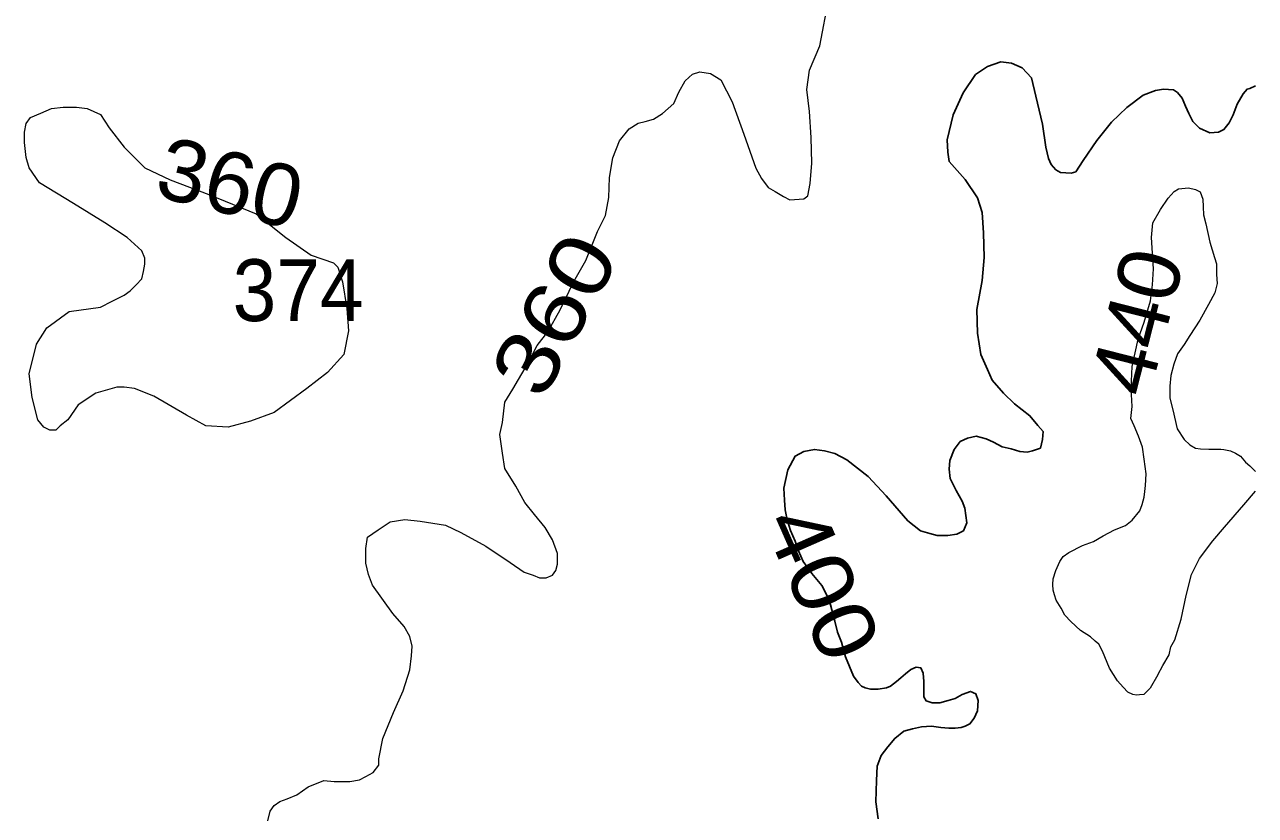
# Model space of a CAD drawing. Extents: x 445.4 to 500, y 8728.7 to 8784.
# Drawn here: x 496.816 to 500, y 8746.525 to 8748.572 of the extents above; entities that cross this region are included whole.
import ezdxf
from ezdxf.enums import TextEntityAlignment as Align

# ---------------------------------------------------------------- set-up
doc = ezdxf.new("R2010")
doc.units = 0
doc.header["$LTSCALE"] = 0.064
doc.layers.add('1', color=7, linetype='Continuous', lineweight=25)
doc.layers.add('2', color=7, linetype='Continuous', lineweight=13)
doc.layers.add('21', color=7, linetype='Continuous')
doc.layers.add('61', color=7, linetype='Continuous')

msp = doc.modelspace()

# ---------------------------------------------------------------- linework, layer by layer
at = {"layer": '1'}
for points in [[(499.1336, 8747.2619), (499.1576, 8747.255), (499.1765, 8747.2499), (499.204, 8747.2499), (499.228, 8747.2533), (499.2451, 8747.2619), (499.2537, 8747.2824), (499.2485, 8747.3201), (499.2417, 8747.3389), (499.2262, 8747.3663), (499.2108, 8747.3971), (499.2074, 8747.4211), (499.2091, 8747.4433), (499.2211, 8747.4724), (499.2365, 8747.493), (499.2554, 8747.5015), (499.2777, 8747.5067), (499.3034, 8747.4998), (499.3223, 8747.4913), (499.3446, 8747.4793), (499.3686, 8747.4742), (499.3909, 8747.4673), (499.4097, 8747.4656), (499.4235, 8747.469), (499.444, 8747.4759), (499.4492, 8747.4981), (499.4509, 8747.5187), (499.4372, 8747.5341), (499.4166, 8747.5597), (499.3772, 8747.5906), (499.348, 8747.618), (499.3192, 8747.6514), (499.3072, 8747.6788), (499.29, 8747.7182), (499.2814, 8747.7729), (499.2797, 8747.8346), (499.2934, 8747.9099), (499.2986, 8747.9692), (499.2969, 8748.0325), (499.2935, 8748.0856), (499.2815, 8748.1232), (499.2489, 8748.1712), (499.2215, 8748.202), (499.2078, 8748.2174), (499.2043, 8748.2414), (499.2026, 8748.2739), (499.218, 8748.3382), (499.2437, 8748.3947), (499.2763, 8748.4426), (499.3072, 8748.4632), (499.3415, 8748.4752), (499.3689, 8748.4717), (499.3964, 8748.4598), (499.4204, 8748.4341), (499.4324, 8748.3861), (499.4495, 8748.3143), (499.4581, 8748.2543), (499.465, 8748.2252), (499.4718, 8748.2098), (499.4838, 8748.1961), (499.4958, 8748.1893), (499.5233, 8748.1876), (499.5353, 8748.191), (499.5541, 8748.2201), (499.5902, 8748.2715), (499.6279, 8748.3194), (499.6673, 8748.357), (499.7093, 8748.3894), (499.7419, 8748.4014), (499.7625, 8748.4048), (499.7882, 8748.4031), (499.7985, 8748.3963), (499.8105, 8748.3809), (499.8191, 8748.3603), (499.8277, 8748.3415), (499.8379, 8748.321), (499.8551, 8748.3038), (499.8825, 8748.2919), (499.9048, 8748.2936), (499.9185, 8748.3004), (499.9323, 8748.3175), (499.9425, 8748.3381), (499.9528, 8748.3655), (499.9683, 8748.3929), (499.9786, 8748.4048), (499.9854, 8748.4066), (500, 8748.4131)], [(499.0243, 8746.5166), (499.0181, 8746.5609), (499.0197, 8746.6159), (499.0212, 8746.6526), (499.0319, 8746.6801), (499.0488, 8746.703), (499.0671, 8746.7244), (499.0901, 8746.7437), (499.1131, 8746.7498), (499.1361, 8746.7544), (499.1621, 8746.7559), (499.1866, 8746.7528), (499.2065, 8746.7513), (499.2233, 8746.7513), (499.2387, 8746.7528), (499.2494, 8746.7559), (499.2616, 8746.762), (499.2723, 8746.7773), (499.2815, 8746.7956), (499.2831, 8746.8231), (499.2769, 8746.84), (499.2631, 8746.8461), (499.2417, 8746.8384), (499.2233, 8746.8277), (499.205, 8746.8231), (499.1835, 8746.817), (499.1636, 8746.817), (499.1483, 8746.8216), (499.1422, 8746.8323), (499.1422, 8746.8507), (499.1422, 8746.8721), (499.1407, 8746.8935), (499.1345, 8746.9072), (499.1223, 8746.9087), (499.1085, 8746.9026), (499.0947, 8746.8919), (499.0825, 8746.8812), (499.0718, 8746.8721), (499.0564, 8746.8598), (499.0457, 8746.8552), (499.0243, 8746.8522), (499.0044, 8746.8522), (498.9906, 8746.8552), (498.9814, 8746.8598), (498.9722, 8746.869), (498.96, 8746.8858), (498.9398, 8746.9355), (498.9296, 8746.9734), (498.9193, 8746.9991), (498.9124, 8747.0282), (498.897, 8747.083), (498.8781, 8747.1206), (498.8524, 8747.1515), (498.8301, 8747.1823), (498.8181, 8747.2097), (498.8095, 8747.2353), (498.7975, 8747.2627), (498.789, 8747.2901), (498.7838, 8747.3158), (498.7821, 8747.3415), (498.7804, 8747.3723), (498.7907, 8747.4194), (498.8095, 8747.4553), (498.8318, 8747.4673), (498.8593, 8747.4724), (498.885, 8747.469), (498.9124, 8747.4622), (498.9433, 8747.4451), (498.9982, 8747.4023), (499.0445, 8747.3526), (499.1011, 8747.2876), (499.1336, 8747.2619)]]:
    msp.add_lwpolyline(points, dxfattribs=at)
at = {"layer": '2'}
for points in [[(498.7391, 8748.15), (498.758, 8748.1395), (498.779, 8748.1269), (498.7958, 8748.1186), (498.8315, 8748.1206), (498.842, 8748.129), (498.8483, 8748.1604), (498.8525, 8748.2128), (498.8504, 8748.2799), (498.8462, 8748.3469), (498.8399, 8748.4035), (498.8462, 8748.4537), (498.8735, 8748.5166), (498.8965, 8748.6402)], [(497.4449, 8746.5114), (497.4512, 8746.5365), (497.4617, 8746.5512), (497.4764, 8746.5616), (497.4953, 8746.5679), (497.5205, 8746.5784), (497.5498, 8746.5994), (497.5897, 8746.6153), (497.617, 8746.6132), (497.6569, 8746.6132), (497.6821, 8746.6174), (497.6989, 8746.6258), (497.7178, 8746.6363), (497.7325, 8746.6551), (497.7325, 8746.6719), (497.7429, 8746.7243), (497.7702, 8746.7913), (497.7954, 8746.8479), (497.8122, 8746.9023), (497.8164, 8746.938), (497.8185, 8746.9631), (497.8122, 8746.9882), (497.7975, 8747.0146), (497.7681, 8747.0481), (497.7157, 8747.1214), (497.7052, 8747.1487), (497.6989, 8747.178), (497.6989, 8747.2157), (497.7031, 8747.245), (497.7304, 8747.2639), (497.7618, 8747.2848), (497.7996, 8747.2911), (497.8395, 8747.2869), (497.9046, 8747.2765), (497.9444, 8747.2576), (498.0095, 8747.222), (498.0724, 8747.1801), (498.1081, 8747.1549), (498.1312, 8747.1466), (498.148, 8747.1403), (498.1648, 8747.1403), (498.1816, 8747.1466), (498.19, 8747.1591), (498.1942, 8747.1759), (498.1942, 8747.2031), (498.1816, 8747.2387), (498.1627, 8747.2702), (498.1354, 8747.3037), (498.1102, 8747.3351), (498.0871, 8747.377), (498.0583, 8747.4228), (498.052, 8747.4626), (498.0457, 8747.5107), (498.052, 8747.5422), (498.0583, 8747.5945), (498.0793, 8747.6281), (498.1171, 8747.693), (498.1422, 8747.7412), (498.1695, 8747.7768), (498.201, 8747.8334), (498.2367, 8747.9067), (498.2682, 8747.9612), (498.2979, 8748.0359), (498.3189, 8748.0778), (498.3273, 8748.1239), (498.3294, 8748.1762), (498.3378, 8748.2265), (498.3546, 8748.2705), (498.3797, 8748.3019), (498.4028, 8748.3166), (498.4217, 8748.3208), (498.4427, 8748.3271), (498.4658, 8748.3417), (498.4957, 8748.3678), (498.5083, 8748.3972), (498.5251, 8748.4265), (498.544, 8748.4433), (498.5628, 8748.4496), (498.5901, 8748.4454), (498.6174, 8748.4286), (498.6468, 8748.372), (498.6762, 8748.2882), (498.7077, 8748.2003), (498.7224, 8748.173), (498.7391, 8748.15)], [(499.7479, 8746.8887), (499.7275, 8746.8542), (499.7152, 8746.8413), (499.7115, 8746.8382), (499.7004, 8746.837), (499.6923, 8746.8364), (499.6831, 8746.8382), (499.6701, 8746.8444), (499.6578, 8746.8573), (499.643, 8746.8739), (499.6226, 8746.906), (499.6047, 8746.9503), (499.5947, 8746.9686), (499.5854, 8746.9766), (499.5731, 8746.9871), (499.5478, 8747.0037), (499.5225, 8747.0271), (499.507, 8747.0432), (499.4972, 8747.0616), (499.4848, 8747.082), (499.4803, 8747.0959), (499.4765, 8747.1083), (499.4759, 8747.123), (499.4772, 8747.1378), (499.484, 8747.1594), (499.4944, 8747.1822), (499.5025, 8747.1951), (499.5173, 8747.2056), (499.5526, 8747.2238), (499.581, 8747.2343), (499.6063, 8747.2485), (499.6353, 8747.2639), (499.6637, 8747.2756), (499.6816, 8747.2891), (499.7008, 8747.3131), (499.7071, 8747.3301), (499.7126, 8747.3486), (499.7139, 8747.3634), (499.7157, 8747.3794), (499.7176, 8747.4089), (499.712, 8747.4476), (499.7077, 8747.4778), (499.6978, 8747.5067), (499.6861, 8747.5338), (499.6781, 8747.5523), (499.6813, 8747.5831), (499.6787, 8747.63), (499.6813, 8747.6873), (499.697, 8747.7576), (499.7126, 8747.8018), (499.7283, 8747.8565), (499.7335, 8747.8981), (499.7361, 8747.9398), (499.7309, 8748.0205), (499.7346, 8748.0591), (499.7542, 8748.0936), (499.7747, 8748.1224), (499.7896, 8748.1401), (499.8008, 8748.1467), (499.827, 8748.1495), (499.8447, 8748.1448), (499.8568, 8748.1392), (499.8643, 8748.1196), (499.8652, 8748.1001), (499.8662, 8748.0796), (499.8718, 8748.0563), (499.882, 8748.0088), (499.8942, 8747.9687), (499.8998, 8747.9523), (499.8998, 8747.9253), (499.9007, 8747.902), (499.8951, 8747.8778), (499.8783, 8747.847), (499.8559, 8747.807), (499.8307, 8747.7669), (499.8158, 8747.7436), (499.7989, 8747.7196), (499.7887, 8747.6926), (499.7812, 8747.6637), (499.7784, 8747.6358), (499.7784, 8747.605), (499.7868, 8747.5752), (499.798, 8747.5258), (499.8158, 8747.4982), (499.8307, 8747.4842), (499.8447, 8747.4758), (499.8578, 8747.4739), (499.8792, 8747.473), (499.897, 8747.473), (499.911, 8747.473), (499.9184, 8747.4721), (499.9352, 8747.4684), (499.9483, 8747.4628), (499.9614, 8747.4553), (499.9744, 8747.4395), (499.9856, 8747.4302), (500, 8747.4152)], [(499.7479, 8746.8887), (499.7604, 8746.9131), (499.7771, 8746.9412), (499.7811, 8746.9619), (499.7918, 8746.9793), (499.8077, 8747.0333), (499.8208, 8747.094), (499.8351, 8747.1487), (499.8554, 8747.1903), (499.8899, 8747.2355), (499.9197, 8747.2712), (499.9699, 8747.3288), (500, 8747.3643)]]:
    msp.add_lwpolyline(points, dxfattribs=at)
msp.add_lwpolyline([(497.0733, 8748.2547), (497.1271, 8748.201), (497.1924, 8748.1703), (497.2923, 8748.132), (497.4153, 8748.0821), (497.4921, 8748.0208), (497.5574, 8747.9747), (497.615, 8747.9556), (497.6266, 8747.9441), (497.6381, 8747.9057), (497.6496, 8747.8367), (497.6535, 8747.7792), (497.6419, 8747.7178), (497.5997, 8747.6718), (497.5459, 8747.6296), (497.4614, 8747.5683), (497.3999, 8747.5453), (497.3423, 8747.5299), (497.2846, 8747.5338), (497.2347, 8747.5606), (497.1502, 8747.6105), (497.1002, 8747.6296), (497.0733, 8747.6335), (497.0541, 8747.6335), (497.0003, 8747.6181), (496.9542, 8747.5875), (496.9273, 8747.5491), (496.9081, 8747.5338), (496.8966, 8747.5223), (496.8812, 8747.5223), (496.8659, 8747.5299), (496.8505, 8747.5491), (496.8351, 8747.6066), (496.8274, 8747.668), (496.8467, 8747.7447), (496.8735, 8747.7869), (496.9312, 8747.829), (497.0119, 8747.8405), (497.0426, 8747.8559), (497.058, 8747.8635), (497.0733, 8747.8712), (497.0887, 8747.8827), (497.1041, 8747.8981), (497.1194, 8747.9134), (497.1233, 8747.9326), (497.1271, 8747.9517), (497.1271, 8747.9671), (497.1194, 8747.9863), (497.081, 8748.0208), (497.0234, 8748.0591), (496.9427, 8748.109), (496.8543, 8748.1626), (496.8274, 8748.201), (496.8198, 8748.2278), (496.8159, 8748.2662), (496.8159, 8748.293), (496.8198, 8748.316), (496.8313, 8748.3314), (496.8582, 8748.3429), (496.8851, 8748.3544), (496.9158, 8748.3582), (496.9504, 8748.3582), (496.9773, 8748.3544), (497.0119, 8748.339), (497.0349, 8748.3045)], close=True, dxfattribs=at)

# ---------------------------------------------------------------- texts
at = {"layer": '21', "width": 0.95}
msp.add_text('374', height=0.16, dxfattribs=at).set_placement((497.354, 8747.8044))
at = {"layer": '61'}
for s, rotation, width, p in [('360', 346.278, 1.05, (497.329, 8748.0846)), ('360', 61.799, 1.2, (498.2567, 8747.784)), ('440', 75.679, 1.05, (499.771, 8747.7836)), ('400', 293.7, 1.15, (498.8067, 8747.0961))]:
    msp.add_text(s, height=0.16, rotation=rotation, dxfattribs=dict(at, width=width)).set_placement(p, align=Align.CENTER)

doc.saveas('drawing.dxf')
